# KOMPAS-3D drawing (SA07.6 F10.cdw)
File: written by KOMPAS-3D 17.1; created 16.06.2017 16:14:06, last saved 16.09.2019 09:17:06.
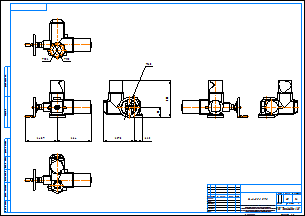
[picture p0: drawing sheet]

Sheet 1: A2, landscape

Title block, sheet 1: name: Привод SA 07.6; material: Сталь 20  ГОСТ 1050-88; mass: 20; sheets: 1; sheet format: A2; stored path: \\adlc.lan\data\АДЛ_ПКД\3D-модели\Поставщики\Сервоприводы AUMA\Электроприводы серии SA\KOMPAS 2D\SA 07.6 F10.cdw

Views: Спереди 1, Проекционный вид 2, Проекционный вид 3, Проекционный вид 4, Проекционный вид 6, Проекционный вид 5
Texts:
  Klimkovich
  ADL
  Рама для чертежей
  Лит-Масса-Масштаб
  Материал-Предприятие
  Масштаб
  Изм.
  Лист
  № докум.
  Подп.
  Дата
  Лит.
  Разраб.
  Пров.
  Т.контр.
  Листов
  Внимание! Данный продукт является объектом авторского права ООО «Торговый Дом АДЛ».
  Запрещается изменение, копирование, распространение
  (в том числе путем копирования на другие сайты и ресурсы в Интернете)
  или любое иное использование информации и объектов без предварительного
  согласия правообладателя (ООО «Торговый Дом АДЛ»).
  Н.контр.
  Утв.
  ООО "Торговый дом АДЛ"
  Изменение
  Номер документа
  Подпись
  Обозначение документа
  Наименование изделия
  Масса изделия по ГОСТ 2.109-73
  Порядковый номер листа
  Общее количество листов в документе
  Характер работы, выполненной лицом, подписавшим документ
  Наименование или индекс предприятия, выпускающего документ
  Инв. № подл.
  Подп. и дата
  Взам. инв. №
  Инв. № дубл.
  Инвентарный номер подлинника по ГОСТ 2.501-68
  Подпись принявшего подлинник в отдел технической документации
  Инвентарный номер подлинника, взамен которого выпущен данный подлинник
  Инвентарный номер дубликата по ГОСТ 2.502-68
  Подпись принявшего дубликат в отдел технической документации
  Справ. №
  Перв. примен.
  Обозначение документа, взамен или на основании которого выпущен данный документ
  Обозначение документа, в котором впервые записан данный документ
  Подпись лица, копировавшего чертеж
  Обозначение формата листа
  !Рама для чертежа
Dimensions and other numbers on the sheet: 160; 288; 62,5; 237,8; 78; 248,7; 264; 102; 110; 1:4; 1; 20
